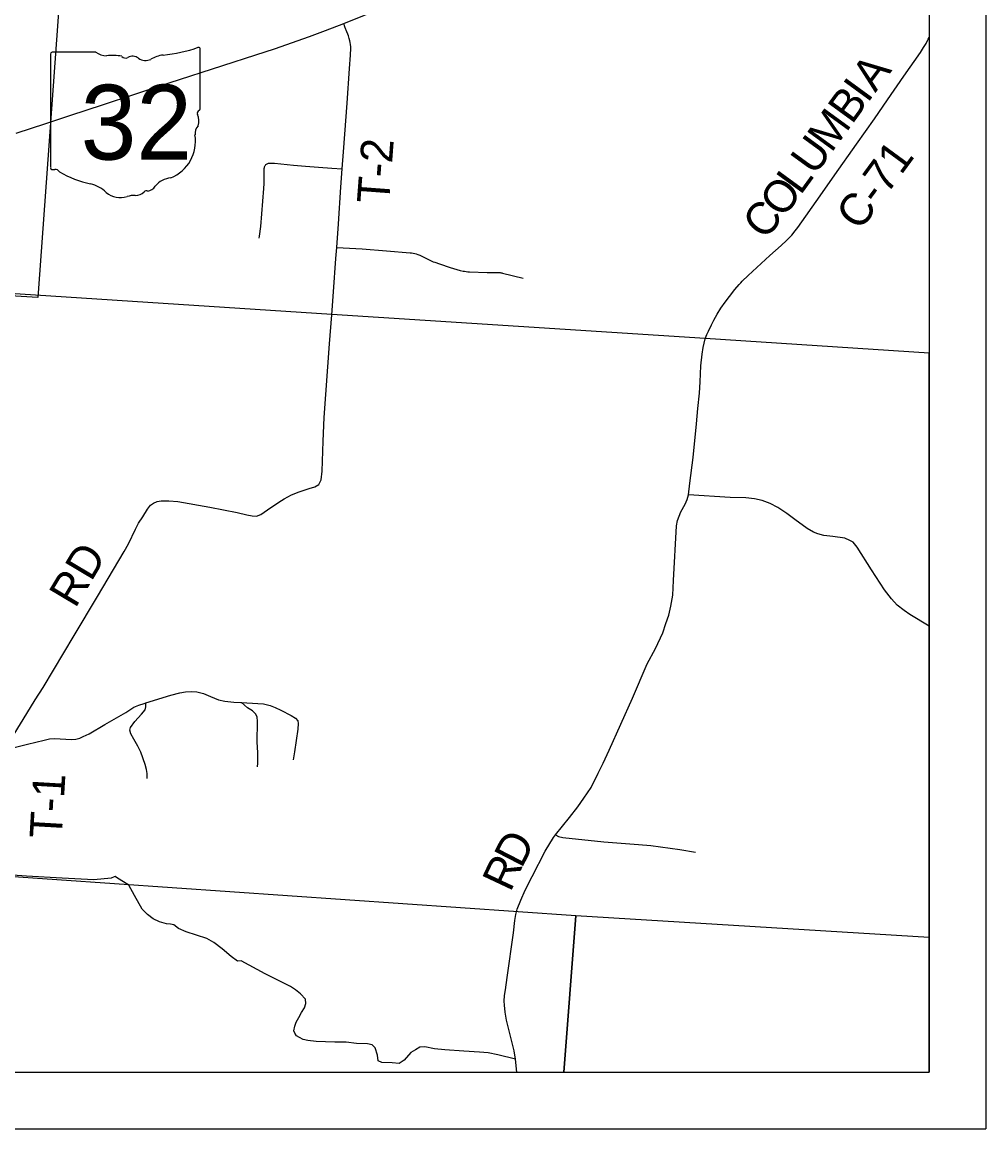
# Model space of a CAD drawing. Extents: x 0 to 34, y 0 to 22.
# Drawn here: x 7.302 to 9, y 14 to 15.949 of the extents above; entities that cross this region are included whole.
import ezdxf

# ---------------------------------------------------------------- set-up
doc = ezdxf.new("R2010")
doc.units = 0
for name, color, linetype in [('GM_X_Corporation', 7, 'Continuous'), ('GM_X_County_Road', 7, 'Continuous'), ('GM_X_County_Road_Text', 7, 'Continuous'), ('GM_X_State_Location', 7, 'Continuous'), ('GM_X_State_Route', 7, 'Continuous'), ('GM_X_State_Shield', 7, 'Continuous'), ('GM_X_Township_Road', 7, 'Continuous'), ('GM_X_Township_Road_Text', 7, 'Continuous'), ('GM_X_Township_Text', 7, 'Continuous'), ('SH_Data', 7, 'Continuous')]:
    doc.layers.add(name, color=color, linetype=linetype)

msp = doc.modelspace()

# ---------------------------------------------------------------- linework, layer by layer
at = {"layer": 'GM_X_Corporation'}
for points in [[(6.3752, 16.5579), (7.4018, 16.494), (7.4044, 16.4938), (7.3299, 15.4642), (6.2993, 15.5265)], [(4.1481, 14.1), (8.9, 14.1), (8.9, 15.3662), (8.5054, 15.3919), (7.8479, 15.4342), (7.082, 15.4841), (6.7558, 15.5053), (6.7389, 15.5063), (6.2987, 15.5286), (5.4088, 15.5882), (4.4836, 15.6492), (4.4152, 15.6505), (4.2922, 15.6568), (4.2674, 15.6579), (4.2558, 15.6584), (4.2352, 15.4905), (4.2113, 15.0848), (4.1846, 14.6877), (4.1741, 14.5315), (4.1604, 14.3288)], [(7.2372, 14.1), (8.2568, 14.1), (8.2775, 14.3752), (7.2616, 14.4454)], [(8.2568, 14.1), (8.9, 14.1), (8.9, 14.3368), (8.2775, 14.3752)]]:
    msp.add_lwpolyline(points, close=True, dxfattribs=at)
at = {"layer": 'GM_X_County_Road'}
for points in [[(8.5057, 15.3914), (8.5086, 15.3991), (8.5112, 15.4049), (8.5165, 15.4161), (8.5207, 15.4243), (8.5269, 15.4351), (8.5334, 15.4456), (8.5408, 15.4563), (8.5482, 15.4663), (8.5579, 15.4783), (8.5655, 15.4873), (8.5681, 15.4903), (8.571, 15.4932), (8.5812, 15.5031), (8.6195, 15.5385), (8.6396, 15.556), (8.6487, 15.5644), (8.6531, 15.5688), (8.6582, 15.5743), (8.6642, 15.5815), (8.6687, 15.5874), (8.7079, 15.6433), (8.7339, 15.6804), (8.7721, 15.7341), (8.8039, 15.7792), (8.8268, 15.8125), (8.8553, 15.8539), (8.8847, 15.8955), (8.8904, 15.9044), (8.8948, 15.9119), (8.8986, 15.9191), (8.9, 15.9224)], [(8.174, 14.1), (8.1715, 14.1228), (8.1689, 14.1376), (8.1593, 14.1776), (8.1557, 14.1913), (8.1534, 14.2057), (8.1522, 14.2179), (8.1514, 14.225), (8.1522, 14.2348), (8.1539, 14.2449), (8.157, 14.2665), (8.1681, 14.3454), (8.1704, 14.3672), (8.1721, 14.3773), (8.1742, 14.3871), (8.1807, 14.4028), (8.1886, 14.4202), (8.2008, 14.4445), (8.2236, 14.4893), (8.2385, 14.5134), (8.2418, 14.5177), (8.254, 14.5333), (8.2668, 14.5482), (8.281, 14.5672), (8.2919, 14.5823), (8.3045, 14.601), (8.3172, 14.6265), (8.326, 14.6441), (8.3365, 14.6667), (8.3778, 14.7585), (8.4035, 14.819), (8.4178, 14.846), (8.431, 14.8735), (8.4364, 14.89), (8.4417, 14.9047), (8.445, 14.9204), (8.4484, 14.9399), (8.45, 14.9656), (8.4551, 15.0618), (8.4567, 15.0713), (8.4626, 15.0869), (8.4701, 15.1001), (8.4739, 15.1087), (8.4762, 15.1167), (8.4787, 15.1374), (8.4846, 15.1827), (8.49, 15.2417), (8.4924, 15.2685), (8.4953, 15.2956), (8.4969, 15.3155), (8.4978, 15.3437), (8.5001, 15.3647), (8.5018, 15.3762), (8.5057, 15.3914)]]:
    msp.add_lwpolyline(points, dxfattribs=at)
at = {"layer": 'GM_X_State_Route'}
msp.add_lwpolyline([(7.2917, 15.7539), (7.3441, 15.7709), (7.3883, 15.7856), (7.4441, 15.8038), (7.5008, 15.8223), (7.5616, 15.8421), (7.6557, 15.8731), (7.714, 15.8919), (7.7468, 15.9025), (7.8086, 15.9238), (7.8367, 15.9343), (7.8688, 15.9466), (7.9053, 15.9614), (7.935, 15.9738), (7.9627, 15.986), (7.9967, 16.0017), (8.0093, 16.0076)], dxfattribs=at)
at = {"layer": 'GM_X_State_Shield'}
for p, q in [((7.3524, 15.8931), (7.3524, 15.693)), ((7.4322, 15.8965), (7.355, 15.8965)), ((7.616, 15.7968), (7.616, 15.9015)), ((7.616, 15.7968), (7.616, 15.7968))]:
    msp.add_line(p, q, dxfattribs=at)
for centre, radius, start, end in [((7.3554, 15.8935), 0.00305, 98.1301, 188.1301), ((7.4506, 15.9198), 0.0296, 231.6195, 271.1119), ((7.4604, 15.7842), 0.1064, 80.4867, 94.9883), ((7.4846, 15.8945), 0.00855, 219.7921, 297.1024), ((7.4971, 15.8714), 0.0178, 54.4667, 119.1411), ((7.5578, 15.8354), 0.0563, 97.3462, 120.7689), ((7.5221, 16.1694), 0.2796, 275.8445, 288.9065), ((7.6131, 15.9019), 0.00294, 351.8621, 97.738), ((7.52, 15.9031), 0.0214, 233.8562, 294.8282), ((7.6154, 15.7891), 0.00454, 107.944, 210.337), ((7.6129, 15.7964), 0.00314, 289.6038, 7.7341), ((7.5865, 15.7759), 0.0273, 340.033, 23.6496), ((7.5378, 15.7397), 0.0699, 292.3089, 8.9858), ((7.6266, 15.753), 0.0198, 136.8065, 186.9296), ((7.3554, 15.6925), 0.00308, 171.9584, 258.3066), ((7.3559, 15.713), 0.0235, 267.339, 280.6039), ((7.3607, 15.6814), 0.00848, 29.7484, 93.2717), ((7.4678, 15.8612), 0.2019, 240.4129, 257.1985), ((7.5673, 15.6368), 0.0383, 94.4031, 142.5768), ((7.4076, 15.6031), 0.0632, 47.1842, 75.836), ((7.5187, 15.6736), 0.0226, 282.8732, 323.2771), ((7.4759, 15.6804), 0.0401, 230.7004, 286.2918), ((7.4991, 15.6112), 0.0329, 85.6951, 111.2099), ((7.502, 15.6654), 0.0214, 268.777, 315.5493), ((7.5213, 15.6461), 0.00601, 65.7517, 132.6484)]:
    msp.add_arc(centre, radius, start, end, dxfattribs=at)
at = {"layer": 'GM_X_Township_Road'}
for points in [[(7.8727, 15.9362), (7.8709, 15.9408), (7.8688, 15.9466)], [(7.879, 15.8677), (7.8806, 15.8908), (7.8809, 15.895), (7.8812, 15.8996), (7.8812, 15.9028), (7.8811, 15.9057), (7.8808, 15.9099), (7.8803, 15.9134), (7.8797, 15.9165), (7.8786, 15.9205), (7.877, 15.9251), (7.8731, 15.9353), (7.8727, 15.9362)], [(7.8481, 15.4337), (7.8507, 15.474), (7.855, 15.5331), (7.8567, 15.5526), (7.8597, 15.5943), (7.864, 15.6583), (7.866, 15.6907), (7.8684, 15.7209), (7.8709, 15.7522), (7.8748, 15.8064), (7.879, 15.8677)], [(7.72, 15.5688), (7.7204, 15.5723), (7.7228, 15.5893), (7.7248, 15.6115), (7.7281, 15.6564), (7.7281, 15.6577), (7.7286, 15.6637), (7.7287, 15.6656), (7.7287, 15.6892), (7.7288, 15.6912), (7.7291, 15.693), (7.7294, 15.6943), (7.73, 15.6958), (7.7305, 15.6967), (7.731, 15.6973), (7.7318, 15.6983), (7.7329, 15.6991), (7.7338, 15.6998), (7.735, 15.7004), (7.7366, 15.7008), (7.7382, 15.701), (7.7404, 15.701), (7.7428, 15.7009), (7.7471, 15.7006), (7.7802, 15.6973), (7.8014, 15.6955), (7.8243, 15.6938), (7.848, 15.6918), (7.866, 15.6907)], [(7.8567, 15.5526), (7.9015, 15.5498), (7.944, 15.5463), (7.9857, 15.5431), (7.9883, 15.5428), (7.9912, 15.5424), (7.9939, 15.5419), (7.9967, 15.5411), (7.9996, 15.5401), (8.0027, 15.5389), (8.0076, 15.5367), (8.0207, 15.5299), (8.024, 15.5284), (8.0265, 15.5273), (8.0292, 15.5263), (8.0373, 15.5233), (8.0565, 15.5171), (8.0742, 15.512), (8.079, 15.5109), (8.0817, 15.5105), (8.0845, 15.51), (8.0874, 15.5096), (8.0902, 15.5093), (8.1213, 15.5085), (8.1443, 15.508), (8.1458, 15.5078), (8.1472, 15.5075), (8.1488, 15.5071), (8.1847, 15.4984)], [(7.2885, 14.6953), (7.3105, 14.7317), (7.3252, 14.7554), (7.3395, 14.7773), (7.3941, 14.8689), (7.435, 14.9377), (7.4728, 15.0009), (7.4822, 15.0167), (7.4896, 15.0305), (7.5019, 15.0561), (7.5076, 15.0669), (7.5147, 15.0778), (7.5231, 15.0915), (7.5284, 15.0982), (7.5337, 15.1021), (7.5405, 15.1047), (7.5472, 15.1062), (7.5605, 15.1064), (7.5769, 15.1047), (7.6329, 15.0949), (7.6811, 15.0857), (7.6981, 15.0814), (7.7075, 15.0796), (7.7153, 15.0794), (7.7226, 15.0821), (7.7347, 15.0902), (7.7543, 15.1039), (7.7639, 15.1094), (7.7766, 15.1164), (7.7903, 15.1219), (7.8077, 15.1278), (7.8181, 15.1309), (7.8248, 15.135), (7.8289, 15.1432), (7.8307, 15.1583), (7.8324, 15.2115), (7.8346, 15.2527), (7.8439, 15.3825), (7.8481, 15.4337)], [(8.9, 14.8856), (8.8662, 14.9057), (8.8558, 14.9131), (8.8439, 14.9225), (8.8338, 14.9333), (8.8217, 14.9495), (8.7985, 14.9846), (8.7735, 15.0247), (8.7661, 15.0332), (8.7603, 15.0363), (8.7517, 15.0404), (8.7306, 15.0433), (8.7144, 15.0453), (8.704, 15.048), (8.6962, 15.051), (8.6854, 15.0573), (8.6633, 15.0732), (8.6492, 15.084), (8.6336, 15.0944), (8.6201, 15.1013), (8.6062, 15.1067), (8.5925, 15.1097), (8.5774, 15.1115), (8.5497, 15.1119), (8.4762, 15.1167)], [(7.5172, 14.7493), (7.52, 14.7502), (7.5641, 14.764), (7.5803, 14.768), (7.59, 14.7699), (7.6006, 14.7705), (7.6101, 14.7697), (7.6221, 14.7668), (7.634, 14.7617), (7.6482, 14.7559), (7.6597, 14.7532), (7.6751, 14.7514), (7.6878, 14.7512)], [(7.2792, 14.6724), (7.2862, 14.6713), (7.3117, 14.6775), (7.3412, 14.6846), (7.3507, 14.687), (7.3594, 14.6875), (7.3791, 14.6862), (7.3894, 14.686), (7.3967, 14.6864), (7.404, 14.6881), (7.4099, 14.6909), (7.4202, 14.696), (7.4479, 14.7122), (7.4852, 14.7336), (7.4989, 14.7425), (7.5078, 14.7464), (7.5172, 14.7493)], [(7.5228, 14.617), (7.5228, 14.6261), (7.5214, 14.633), (7.519, 14.6419), (7.5113, 14.6634), (7.5062, 14.6741), (7.4991, 14.6864), (7.4939, 14.6956), (7.4923, 14.7022), (7.4931, 14.7071), (7.5011, 14.7173), (7.5129, 14.7306), (7.5188, 14.7383), (7.5202, 14.7435), (7.52, 14.7502)], [(7.6878, 14.7512), (7.6888, 14.7512), (7.7174, 14.7492), (7.7275, 14.7483), (7.7391, 14.7456), (7.7482, 14.7421), (7.7579, 14.7373), (7.7761, 14.7279), (7.7838, 14.7233), (7.7881, 14.7188), (7.7885, 14.714), (7.788, 14.704), (7.7822, 14.6642), (7.7799, 14.6502)], [(7.7168, 14.6378), (7.7174, 14.6443), (7.7174, 14.6502), (7.7174, 14.6628), (7.7166, 14.6808), (7.7172, 14.7176), (7.7164, 14.7259), (7.7135, 14.731), (7.7079, 14.736), (7.6996, 14.7415), (7.6888, 14.7512)], [(8.2418, 14.5177), (8.2471, 14.5149), (8.2548, 14.5132), (8.3271, 14.5057), (8.3882, 14.5008), (8.4098, 14.499), (8.4607, 14.4923), (8.4884, 14.4872)], [(7.5005, 14.411), (7.4904, 14.4292), (7.4808, 14.4349), (7.4701, 14.4414), (7.4665, 14.4442), (7.4643, 14.444), (7.4593, 14.4416), (7.4287, 14.4384), (7.3731, 14.4416), (7.3103, 14.4448), (7.2692, 14.4482)], [(7.9357, 14.117), (7.9298, 14.1199), (7.9284, 14.1299), (7.9244, 14.1425), (7.9192, 14.1477), (7.9107, 14.1499), (7.8913, 14.1502), (7.8729, 14.1524), (7.8533, 14.1528), (7.8201, 14.1537), (7.8059, 14.1557), (7.7972, 14.1574), (7.7908, 14.1608), (7.7859, 14.1637), (7.7826, 14.1683), (7.7811, 14.1727), (7.7826, 14.1811), (7.7853, 14.1878), (7.7899, 14.196), (7.7946, 14.2052), (7.7995, 14.2132), (7.8022, 14.221), (7.8017, 14.2284), (7.7927, 14.2376), (7.7838, 14.245), (7.7748, 14.2505), (7.7306, 14.273), (7.6881, 14.2961), (7.6819, 14.2956), (7.6704, 14.3033), (7.6547, 14.3169), (7.6401, 14.3283), (7.6276, 14.3354), (7.5915, 14.3471), (7.5777, 14.3526), (7.5695, 14.3591), (7.5639, 14.3606), (7.5568, 14.3611), (7.5443, 14.3648), (7.5332, 14.3698), (7.523, 14.3775), (7.514, 14.3867), (7.5005, 14.411)], [(8.1715, 14.1228), (8.1404, 14.1302), (8.1235, 14.1336), (8.1079, 14.1349), (8.0806, 14.1368), (8.0472, 14.1394), (8.0286, 14.1411), (8.0116, 14.1445), (8.0028, 14.1437), (7.995, 14.1394), (7.9873, 14.1345), (7.9753, 14.121), (7.9667, 14.1151), (7.9539, 14.1164), (7.9357, 14.117)]]:
    msp.add_lwpolyline(points, dxfattribs=at)
at = {"layer": 'GM_X_Township_Text'}
msp.add_lwpolyline([(8.9, 15.3662), (8.5054, 15.3919), (7.8479, 15.4342), (7.082, 15.4841), (6.7558, 15.5053), (6.7389, 15.5063), (6.2987, 15.5286), (5.4088, 15.5882), (4.4836, 15.6492), (4.4152, 15.6505), (4.2922, 15.6568), (4.2674, 15.6579), (4.2558, 15.6584), (4.2352, 15.4905), (4.2113, 15.0848), (4.1846, 14.6877), (4.1741, 14.5315), (4.1604, 14.3288), (4.1481, 14.1)], dxfattribs=at)
at = {"layer": 'SH_Data'}
for p, q in [((9, 21), (9, 14)), ((8.9, 20.9), (8.9, 14.1)), ((4.1481, 14.1), (8.9, 14.1)), ((2, 14), (9, 14))]:
    msp.add_line(p, q, dxfattribs=at)

# ---------------------------------------------------------------- texts
at = {"layer": 'GM_X_County_Road_Text'}
for s, height, rotation, p in [('A', 0.0568, 53.2168, (8.8053, 15.8241)), ('I', 0.0568, 53.929, (8.7916, 15.8054)), ('B', 0.0568, 53.9267, (8.7641, 15.7677)), ('M', 0.0568, 53.9311, (8.7278, 15.7178)), ('U', 0.0568, 53.9306, (8.6984, 15.6774)), ('C-71', 0.05682, 53.7484, (8.7782, 15.5798)), ('L', 0.0568, 53.9293, (8.6734, 15.6431)), ('O', 0.0568, 53.2941, (8.6431, 15.6024)), ('C', 0.0568, 49.2526, (8.6099, 15.5637)), ('D', 0.0568, 62.7654, (8.182, 14.4572)), ('R', 0.0568, 64.7931, (8.1623, 14.4155))]:
    msp.add_text(s, height=height, rotation=rotation, dxfattribs=at).set_placement(p)
at = {"layer": 'GM_X_State_Location'}
for s in ['s', 'r']:
    msp.add_text(s, height=0.000189, dxfattribs=at).set_placement((7.4812, 15.7797))
msp.add_text('32', height=0.000189, rotation=0, dxfattribs=at).set_placement((7.4336, 15.7659))
at = {"layer": 'GM_X_State_Shield'}
msp.add_text('32', height=0.13184, dxfattribs=at).set_placement((7.4055, 15.7071))
at = {"layer": 'GM_X_Township_Road_Text'}
for s, rotation, p in [('T-2', 85.7113, (7.9486, 15.6283)), ('RD', 59.2073, (7.3959, 14.9153)), ('T-1', 86.6532, (7.372, 14.5105))]:
    msp.add_text(s, height=0.05682, rotation=rotation, dxfattribs=at).set_placement(p)

doc.saveas('drawing.dxf')
